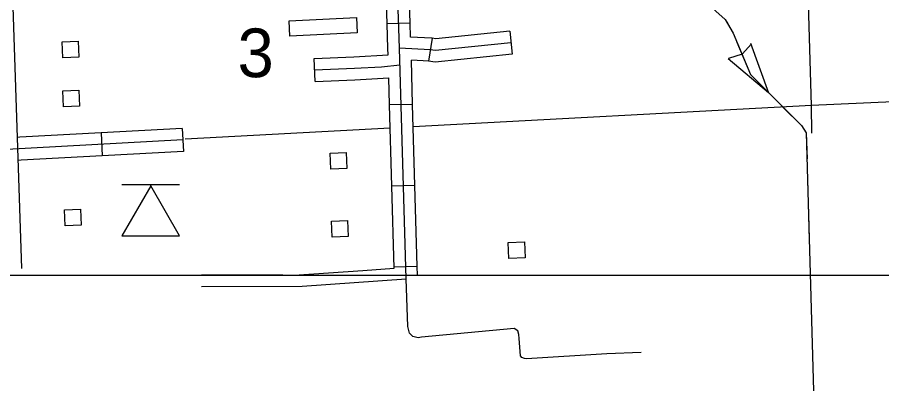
# Model space of a CAD drawing. Extents: x 1671357 to 13005564, y 567358 to 14261451.
# Drawn here: x 12758279.26 to 12758289.9, y 14259852.54 to 14259857.14 of the extents above; entities that cross this region are included whole.
import ezdxf

# ---------------------------------------------------------------- set-up
doc = ezdxf.new("R2010")
doc.units = 0
for name, color, linetype in [('10', 7, 'Continuous'), ('2', 7, 'Continuous'), ('32', 7, 'Continuous'), ('35', 7, 'Continuous'), ('5', 7, 'Continuous'), ('56', 7, 'Continuous')]:
    doc.layers.add(name, color=color, linetype=linetype)

msp = doc.modelspace()

# ---------------------------------------------------------------- linework, layer by layer
at = {"layer": '10'}
msp.add_lwpolyline([(12758279.317, 14259854.045), (12758279.194, 14259857.769), (12758279.161, 14259860.283), (12758279.175, 14259860.3), (12758279.205, 14259860.323), (12758279.319, 14259860.362), (12758279.545, 14259860.392), (12758280.582, 14259860.457), (12758281.163, 14259860.501)], dxfattribs=at)
at = {"layer": '2'}
msp.add_line((12758241.074, 14259853.963), (12758347.684, 14259853.963), dxfattribs=at)
at = {"layer": '32'}
for p, q in [((12758284.098, 14259857.069), (12758283.814, 14259857.059)), ((12758285.325, 14259856.968), (12758285.354, 14259856.685)), ((12758284.367, 14259856.882), (12758284.322, 14259856.602)), ((12758282.927, 14259856.35), (12758282.915, 14259856.634)), ((12758284.128, 14259856.068), (12758283.844, 14259856.06)), ((12758280.293, 14259855.717), (12758280.308, 14259855.433)), ((12758281.291, 14259855.772), (12758281.307, 14259855.488)), ((12758284.157, 14259855.069), (12758283.873, 14259855.061)), ((12758284.185, 14259854.069), (12758283.901, 14259854.061))]:
    msp.add_line(p, q, dxfattribs=at)
for points in [[(12758286.519, 14259852.992), (12758285.529, 14259852.933), (12758285.504, 14259852.934), (12758285.471, 14259852.946), (12758285.457, 14259852.968), (12758285.438, 14259853.18), (12758285.436, 14259853.23), (12758285.423, 14259853.275), (12758285.378, 14259853.305), (12758284.236, 14259853.198), (12758284.196, 14259853.191), (12758284.129, 14259853.205), (12758284.09, 14259853.246), (12758284.068, 14259853.329), (12758284.048, 14259853.917), (12758283.966, 14259856.761), (12758283.829, 14259860.866)], [(12758283.814, 14259857.059), (12758283.781, 14259858.059)], [(12758284.098, 14259857.069), (12758284.065, 14259858.068)], [(12758283.826, 14259856.678), (12758283.824, 14259856.757), (12758283.814, 14259857.059)], [(12758284.104, 14259856.897), (12758284.098, 14259857.069)], [(12758285.325, 14259856.968), (12758284.415, 14259856.874), (12758284.367, 14259856.882)], [(12758284.367, 14259856.882), (12758284.359, 14259856.883), (12758284.104, 14259856.897)], [(12758285.339, 14259856.826), (12758284.411, 14259856.731), (12758284.344, 14259856.742), (12758283.966, 14259856.761)], [(12758282.915, 14259856.634), (12758283.404, 14259856.655), (12758283.826, 14259856.678)], [(12758285.354, 14259856.685), (12758284.407, 14259856.588), (12758284.322, 14259856.602)], [(12758282.921, 14259856.492), (12758283.411, 14259856.513), (12758283.744, 14259856.531), (12758283.972, 14259856.554)], [(12758284.329, 14259856.6), (12758284.113, 14259856.612)], [(12758284.128, 14259856.068), (12758284.113, 14259856.612)], [(12758282.927, 14259856.35), (12758283.418, 14259856.371), (12758283.835, 14259856.394)], [(12758283.844, 14259856.06), (12758283.835, 14259856.394)], [(12758283.873, 14259855.061), (12758283.844, 14259856.06)], [(12758284.157, 14259855.069), (12758284.128, 14259856.068)], [(12758280.293, 14259855.717), (12758279.294, 14259855.662)], [(12758281.291, 14259855.772), (12758280.293, 14259855.717)], [(12758281.299, 14259855.63), (12758279.059, 14259855.507)], [(12758279.294, 14259855.662), (12758279.264, 14259855.661)], [(12758281.307, 14259855.488), (12758280.308, 14259855.433)], [(12758279.31, 14259855.379), (12758279.273, 14259855.377)], [(12758280.308, 14259855.433), (12758279.31, 14259855.379)], [(12758283.902, 14259854.049), (12758283.873, 14259855.061)], [(12758284.185, 14259854.069), (12758284.157, 14259855.069)], [(12758281.528, 14259853.965), (12758282.528, 14259853.969)], [(12758282.672, 14259853.963), (12758283.517, 14259854.022)], [(12758283.517, 14259854.022), (12758283.902, 14259854.049)], [(12758284.188, 14259853.963), (12758284.185, 14259854.069)], [(12758282.768, 14259853.827), (12758284.048, 14259853.917)], [(12758281.528, 14259853.823), (12758282.768, 14259853.827)], [(12758286.943, 14259853.01), (12758286.519, 14259852.992)]]:
    msp.add_lwpolyline(points, dxfattribs=at)
at = {"layer": '35'}
for p, q in [((12758288.301, 14259856.814), (12758288.185, 14259856.686)), ((12758288.287, 14259856.821), (12758288.509, 14259856.21)), ((12758288.509, 14259856.21), (12758288.011, 14259856.629)), ((12758288.183, 14259856.685), (12758288.018, 14259856.632))]:
    msp.add_line(p, q, dxfattribs=at)
for points in [[(12758286.166, 14259860.97), (12758286.689, 14259859.515), (12758286.919, 14259858.905), (12758287.036, 14259858.546), (12758287.097, 14259858.307), (12758287.165, 14259858.161), (12758287.733, 14259857.357), (12758287.862, 14259857.217), (12758287.976, 14259857.113), (12758288.075, 14259856.944), (12758288.287, 14259856.435), (12758288.916, 14259855.806), (12758288.974, 14259855.717), (12758289.063, 14259852.538)], [(12758287.535, 14259857.637), (12758287.733, 14259857.357), (12758287.862, 14259857.217), (12758287.976, 14259857.113), (12758288.008, 14259857.059)], [(12758288.12, 14259856.836), (12758288.287, 14259856.435), (12758288.511, 14259856.212)], [(12758288.687, 14259856.035), (12758288.916, 14259855.806), (12758288.974, 14259855.717), (12758288.983, 14259855.397)], [(12758288.99, 14259855.147), (12758289.011, 14259854.397)]]:
    msp.add_lwpolyline(points, dxfattribs=at)
at = {"layer": '5'}
for points in [[(12758289.044, 14259855.713), (12758289.038, 14259856.055), (12758288.963, 14259858.564)], [(12758292.51, 14259856.211), (12758289.038, 14259856.055), (12758284.136, 14259855.79)], [(12758283.852, 14259855.775), (12758281.327, 14259855.638)]]:
    msp.add_lwpolyline(points, dxfattribs=at)
at = {"layer": '56'}
for p, q in [((12758280.549, 14259855.081), (12758281.259, 14259855.081)), ((12758280.904, 14259855.062), (12758280.549, 14259854.447)), ((12758280.904, 14259855.062), (12758280.904, 14259855.081)), ((12758281.259, 14259854.447), (12758280.904, 14259855.062)), ((12758280.549, 14259854.447), (12758281.259, 14259854.447))]:
    msp.add_line(p, q, dxfattribs=at)
for points in [[(12758282.618, 14259856.91), (12758282.609, 14259857.099), (12758283.436, 14259857.139), (12758283.445, 14259856.949)], [(12758279.823, 14259856.642), (12758279.815, 14259856.839), (12758280.013, 14259856.847), (12758280.021, 14259856.65)], [(12758279.829, 14259856.037), (12758279.821, 14259856.234), (12758280.019, 14259856.242), (12758280.026, 14259856.045)], [(12758283.121, 14259855.27), (12758283.114, 14259855.467), (12758283.311, 14259855.475), (12758283.319, 14259855.278)], [(12758279.852, 14259854.57), (12758279.844, 14259854.767), (12758280.042, 14259854.775), (12758280.05, 14259854.578)], [(12758283.137, 14259854.432), (12758283.129, 14259854.629), (12758283.326, 14259854.637), (12758283.334, 14259854.44)], [(12758285.314, 14259854.169), (12758285.306, 14259854.366), (12758285.504, 14259854.373), (12758285.512, 14259854.176)]]:
    msp.add_lwpolyline(points, close=True, dxfattribs=at)

# ---------------------------------------------------------------- texts
msp.add_text('3', height=0.6, dxfattribs=at).set_placement((12758281.973, 14259856.403))

doc.saveas('drawing.dxf')
